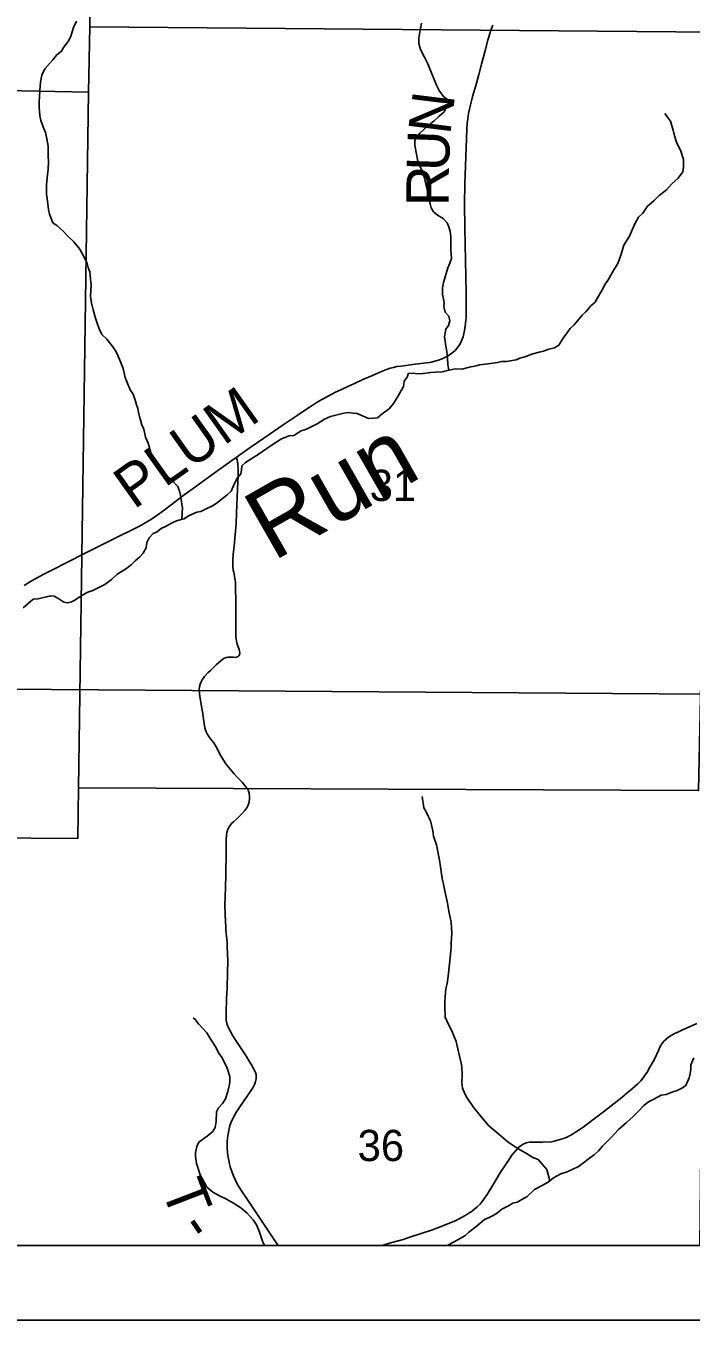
# Model space of a CAD drawing. Extents: x -19.9 to 41.9, y 0 to 32.3.
# Drawn here: x 4.075 to 4.967, y 14 to 15.736 of the extents above; entities that cross this region are included whole.
import ezdxf

# ---------------------------------------------------------------- set-up
doc = ezdxf.new("R2010")
doc.units = 0
for name, color, linetype in [('GM_X_Corporation', 7, 'Continuous'), ('GM_X_County_Road', 7, 'Continuous'), ('GM_X_County_Road_Text', 7, 'Continuous'), ('GM_X_Minor_River', 7, 'Continuous'), ('GM_X_Minor_River_Text', 7, 'Continuous'), ('GM_X_Section', 7, 'Continuous'), ('GM_X_Section_Text', 7, 'Continuous'), ('GM_X_Township_Road', 7, 'Continuous'), ('GM_X_Township_Road_Text', 7, 'Continuous'), ('SH_Data', 7, 'Continuous')]:
    doc.layers.add(name, color=color, linetype=linetype)

msp = doc.modelspace()

# ---------------------------------------------------------------- linework, layer by layer
at = {"layer": 'GM_X_Corporation'}
for points in [[(2.1, 17.918), (2.1, 14.1), (8.9, 14.1), (8.9, 17.8974), (7.9072, 17.9171), (7.5529, 17.9242), (7.3858, 17.9277), (6.9468, 17.937), (6.7, 17.9422), (6.3069, 17.9505), (6.2497, 17.9517), (6.2397, 17.9517), (5.9048, 17.9534), (5.761, 17.9543), (5.4954, 17.9559), (5.0257, 17.9637), (5.0192, 17.8403), (4.9169, 17.8392), (4.2613, 17.8672), (3.984, 17.879), (3.7505, 17.884), (2.973, 17.9007), (2.4715, 17.9106)], [(3.9969, 15.8607), (5.0009, 15.8404), (4.9872, 14.9075), (4.9863, 14.8396), (3.9837, 14.8466)], [(3.9655, 14.1), (4.9783, 14.1), (4.9863, 14.8396), (3.9837, 14.8466)]]:
    msp.add_lwpolyline(points, close=True, dxfattribs=at)
msp.add_lwpolyline([(2.1, 17.918), (2.1, 14.1), (7.8246, 14.1), (7.8518, 15.3043), (7.854, 15.4058), (7.8702, 16.1679), (7.8776, 16.5173), (7.9012, 17.4524), (7.9072, 17.9171)], dxfattribs=at)
at = {"layer": 'GM_X_County_Road'}
msp.add_lwpolyline([(4.0725, 14.9855), (4.0811, 14.9905), (4.0982, 15), (4.1107, 15.0065), (4.1526, 15.0277), (4.1884, 15.0456), (4.227, 15.065), (4.2333, 15.0684), (4.238, 15.0711), (4.2432, 15.0744), (4.2492, 15.0785), (4.2603, 15.0864), (4.2753, 15.098), (4.2872, 15.1069), (4.2993, 15.1156), (4.3193, 15.1303), (4.3508, 15.1529), (4.3569, 15.157), (4.3646, 15.1626), (4.3771, 15.1714), (4.4024, 15.1887), (4.4198, 15.2009), (4.4414, 15.2153), (4.4512, 15.2218), (4.4585, 15.2267), (4.4655, 15.2313), (4.4724, 15.2353), (4.4799, 15.2394), (4.489, 15.2441), (4.4981, 15.2482), (4.5064, 15.2521), (4.5147, 15.2558), (4.5267, 15.2614), (4.5394, 15.2671), (4.5515, 15.2723), (4.5584, 15.275), (4.5631, 15.2766), (4.5678, 15.2779), (4.5722, 15.2789), (4.5779, 15.2797), (4.5967, 15.282), (4.6161, 15.2844), (4.6183, 15.2848), (4.6233, 15.286), (4.6281, 15.2875), (4.633, 15.2894), (4.6376, 15.2915), (4.6405, 15.2932), (4.6443, 15.2957), (4.6477, 15.2984), (4.6507, 15.301), (4.6527, 15.3033), (4.6549, 15.3062), (4.6565, 15.3086), (4.6585, 15.3126), (4.6598, 15.3156), (4.661, 15.3189), (4.6621, 15.3231), (4.663, 15.3275), (4.6639, 15.3335), (4.6648, 15.3408), (4.6651, 15.3452), (4.6653, 15.3585), (4.665, 15.3781), (4.6635, 15.4641), (4.6629, 15.4971), (4.6633, 15.5242), (4.6646, 15.5604), (4.6659, 15.5972), (4.6666, 15.6049), (4.6673, 15.6114), (4.6683, 15.6182), (4.6695, 15.6241), (4.6709, 15.63), (4.6723, 15.6354), (4.6738, 15.6413), (4.6785, 15.6573), (4.6822, 15.6709), (4.6858, 15.6847), (4.6905, 15.7028), (4.6943, 15.7169), (4.6984, 15.7302), (4.701, 15.7368)], dxfattribs=at)
at = {"layer": 'GM_X_Minor_River'}
for points in [[(4.284, 15.074), (4.2844, 15.0831), (4.2847, 15.0892), (4.2834, 15.0975), (4.2822, 15.1066), (4.2809, 15.1119), (4.2786, 15.118), (4.2709, 15.1263), (4.2628, 15.133), (4.2533, 15.1397), (4.249, 15.1461), (4.2455, 15.1552), (4.2427, 15.162), (4.2387, 15.1764), (4.2352, 15.1843), (4.2328, 15.1949), (4.2304, 15.2006), (4.2288, 15.2059), (4.2272, 15.212), (4.226, 15.2177), (4.2248, 15.2226), (4.2232, 15.2275), (4.222, 15.2325), (4.2185, 15.2419), (4.2146, 15.2476), (4.2107, 15.2578), (4.2079, 15.2642), (4.2051, 15.2764), (4.2016, 15.2851), (4.1988, 15.293), (4.1953, 15.2994), (4.1899, 15.3073), (4.1833, 15.3156), (4.1768, 15.322), (4.1737, 15.3288), (4.1713, 15.3345), (4.1681, 15.3439), (4.165, 15.3549), (4.1629, 15.364), (4.1616, 15.3735), (4.1622, 15.3884), (4.1617, 15.3963), (4.1604, 15.4058), (4.1584, 15.4119), (4.1572, 15.4172), (4.1525, 15.4266), (4.1471, 15.4365), (4.139, 15.4462), (4.1313, 15.4537), (4.124, 15.4616), (4.1163, 15.4683), (4.111, 15.4717), (4.1067, 15.4834), (4.1054, 15.4895), (4.1033, 15.5043), (4.1025, 15.51), (4.1023, 15.5229), (4.104, 15.5367), (4.1046, 15.5431), (4.1052, 15.5546), (4.1048, 15.561), (4.1046, 15.5747), (4.1029, 15.5846), (4.1013, 15.593), (4.0989, 15.5982), (4.0969, 15.6039), (4.095, 15.6092), (4.0934, 15.6157), (4.0928, 15.6267), (4.0927, 15.6347), (4.093, 15.6404), (4.0936, 15.6492), (4.0946, 15.6602), (4.0964, 15.6698), (4.1004, 15.6782), (4.1108, 15.6902), (4.1164, 15.6971), (4.1228, 15.7018), (4.1254, 15.7071), (4.1324, 15.7164), (4.135, 15.7221), (4.1386, 15.7336), (4.1426, 15.742)], [(4.6419, 15.2739), (4.6413, 15.2765), (4.6404, 15.2819), (4.6399, 15.2902), (4.639, 15.2993), (4.6378, 15.3062), (4.637, 15.3126), (4.6361, 15.3187), (4.6379, 15.329), (4.6416, 15.334), (4.6434, 15.3405), (4.6418, 15.3466), (4.6368, 15.3518), (4.6351, 15.3594), (4.6354, 15.3644), (4.6346, 15.3693), (4.6334, 15.3761), (4.6333, 15.3845), (4.6347, 15.3918), (4.6404, 15.4116), (4.6434, 15.4178), (4.6456, 15.4239), (4.6451, 15.4296), (4.6446, 15.4357), (4.6444, 15.4536), (4.6435, 15.46), (4.6419, 15.4665), (4.6396, 15.4718), (4.6345, 15.4774), (4.6265, 15.4822), (4.6215, 15.4867), (4.6184, 15.492), (4.6168, 15.4973), (4.6141, 15.5064), (4.6124, 15.5193), (4.6103, 15.5276), (4.6087, 15.5333), (4.606, 15.5413), (4.6032, 15.5477), (4.6005, 15.5545), (4.598, 15.5659), (4.5964, 15.5758), (4.5963, 15.5815), (4.5985, 15.5865), (4.603, 15.5922), (4.6078, 15.5965), (4.6134, 15.6012), (4.622, 15.6085), (4.6291, 15.6147), (4.6355, 15.6205), (4.6384, 15.6259), (4.6414, 15.6309), (4.6402, 15.6373), (4.6352, 15.6407), (4.6294, 15.6482), (4.6255, 15.6565), (4.6212, 15.666), (4.6181, 15.6739), (4.6137, 15.6849), (4.6091, 15.694), (4.604, 15.7042), (4.6016, 15.7121), (4.6015, 15.7197), (4.6025, 15.7251), (4.6054, 15.7396)], [(4.6832, 15.2814), (4.6908, 15.2822), (4.6976, 15.2831), (4.707, 15.2844), (4.7127, 15.2856), (4.7191, 15.2857), (4.7323, 15.2882), (4.7372, 15.2902), (4.7436, 15.2922), (4.7546, 15.2961), (4.7629, 15.2982), (4.7689, 15.2998), (4.7761, 15.3022), (4.7836, 15.3042), (4.7892, 15.3077), (4.7944, 15.3158), (4.8044, 15.33), (4.8097, 15.335), (4.8208, 15.3478), (4.8257, 15.3524), (4.8324, 15.3605), (4.838, 15.3652), (4.8413, 15.3713), (4.8468, 15.3809), (4.8513, 15.3893), (4.8553, 15.3951), (4.8627, 15.4078), (4.8683, 15.4174), (4.8708, 15.4235), (4.873, 15.4296), (4.8766, 15.4419), (4.884, 15.4538), (4.888, 15.4633), (4.8917, 15.4714), (4.8961, 15.4795), (4.9021, 15.4849), (4.9084, 15.4941), (4.9166, 15.5011), (4.9237, 15.5084), (4.9335, 15.5158), (4.9409, 15.5239), (4.9495, 15.5316), (4.9555, 15.5401), (4.9565, 15.5462), (4.9563, 15.5569), (4.9524, 15.5694), (4.9477, 15.5784), (4.9445, 15.5883), (4.9425, 15.5962), (4.9409, 15.6019), (4.9389, 15.608), (4.9351, 15.6136), (4.9316, 15.6185)], [(4.0712, 14.9553), (4.0847, 14.967), (4.0915, 14.9675), (4.1024, 14.9703), (4.1081, 14.9715), (4.113, 14.9712), (4.1191, 14.9675), (4.1256, 14.963), (4.1306, 14.962), (4.1358, 14.9636), (4.1407, 14.9655), (4.1501, 14.9722), (4.158, 14.9765), (4.1644, 14.9785), (4.17, 14.9812), (4.1805, 14.9867), (4.1895, 14.9933), (4.1974, 15.0007), (4.2086, 15.0073), (4.2158, 15.0131), (4.2214, 15.0182), (4.2277, 15.0236), (4.2322, 15.0286), (4.2362, 15.0359), (4.2369, 15.0428), (4.2402, 15.0493), (4.2454, 15.0551), (4.2507, 15.0574), (4.2563, 15.0617), (4.262, 15.0645), (4.271, 15.0695), (4.2766, 15.0719), (4.2819, 15.0735), (4.2872, 15.0747), (4.2928, 15.0786), (4.3041, 15.0838), (4.3094, 15.0846), (4.3165, 15.0881), (4.3252, 15.0921), (4.3312, 15.0964), (4.3383, 15.1018), (4.3446, 15.1068), (4.3499, 15.1119), (4.3546, 15.1222), (4.3587, 15.1299), (4.3632, 15.1349), (4.3638, 15.1402), (4.3645, 15.146), (4.3694, 15.1502), (4.3877, 15.1619), (4.4024, 15.1724), (4.4114, 15.1779), (4.4177, 15.1822), (4.4279, 15.1861), (4.434, 15.1866), (4.4441, 15.1928), (4.4509, 15.1952), (4.4599, 15.1996), (4.4652, 15.2023), (4.4753, 15.2082), (4.4832, 15.2121), (4.4888, 15.2133), (4.4956, 15.2153), (4.5013, 15.2166), (4.5073, 15.2174), (4.5138, 15.2164), (4.5191, 15.2161), (4.526, 15.2127), (4.5343, 15.2094), (4.5415, 15.2096), (4.5464, 15.2104), (4.5524, 15.2154), (4.5618, 15.2224), (4.5677, 15.2294), (4.5733, 15.239), (4.5781, 15.2467), (4.581, 15.2524), (4.5821, 15.2593), (4.5862, 15.2647), (4.588, 15.27), (4.5963, 15.2698), (4.6012, 15.2691), (4.6073, 15.2696), (4.6179, 15.2712), (4.6239, 15.2713), (4.633, 15.2718), (4.6383, 15.2731), (4.6504, 15.2759), (4.6595, 15.2753), (4.6696, 15.2781), (4.6783, 15.2798), (4.6832, 15.2814)], [(4.645, 14.5055), (4.6459, 14.5192), (4.6449, 14.5337), (4.6425, 14.5462), (4.6396, 14.5614), (4.6371, 14.5735), (4.6347, 14.5845), (4.6331, 14.5925), (4.6306, 14.608), (4.6293, 14.6168), (4.6252, 14.6376), (4.6213, 14.649), (4.6204, 14.6562), (4.6172, 14.6695), (4.6141, 14.6759), (4.6117, 14.6816), (4.6082, 14.6869), (4.6061, 14.7021)], [(4.7772, 14.187), (4.7732, 14.2022), (4.7616, 14.2153), (4.7544, 14.2179), (4.7445, 14.2242), (4.7349, 14.2298), (4.7215, 14.2387), (4.7089, 14.2492), (4.6955, 14.2608), (4.6858, 14.272), (4.6747, 14.286), (4.6661, 14.2988), (4.6634, 14.3037), (4.6603, 14.3112), (4.6594, 14.3181), (4.6596, 14.3291), (4.6595, 14.3398), (4.6583, 14.3447), (4.655, 14.3599), (4.6518, 14.3735), (4.6487, 14.3811), (4.6459, 14.3879), (4.6416, 14.3966), (4.6369, 14.4064), (4.6363, 14.4209), (4.6363, 14.4258), (4.6369, 14.4342), (4.6379, 14.4445), (4.6397, 14.4517), (4.6414, 14.4647), (4.6417, 14.4697), (4.6434, 14.4819), (4.645, 14.5002), (4.645, 14.5055)], [(4.3949, 14.1), (4.3922, 14.1058), (4.3878, 14.1191), (4.3839, 14.1278), (4.3797, 14.1345), (4.3716, 14.1436), (4.3631, 14.1507), (4.3532, 14.157), (4.3437, 14.1622), (4.3345, 14.1666), (4.3257, 14.1718), (4.3173, 14.1785), (4.3138, 14.1849), (4.3087, 14.1947), (4.3052, 14.2046), (4.3036, 14.2099), (4.3023, 14.2194), (4.3022, 14.2247), (4.304, 14.2327), (4.3066, 14.2388), (4.3178, 14.2466), (4.3253, 14.2528), (4.3286, 14.2582), (4.33, 14.2666), (4.3306, 14.2792), (4.3332, 14.2849), (4.3384, 14.2907), (4.3425, 14.2969), (4.3457, 14.3068), (4.3479, 14.316), (4.3482, 14.3209), (4.3481, 14.3266), (4.3449, 14.338), (4.3379, 14.3516), (4.3336, 14.358), (4.3286, 14.3675), (4.3227, 14.3765), (4.3173, 14.3855), (4.3123, 14.3912), (4.3065, 14.3976), (4.3023, 14.4028), (4.2991, 14.4053)], [(4.8802, 14.2651), (4.8888, 14.2732), (4.8951, 14.2794), (4.9033, 14.2879), (4.9097, 14.2929), (4.9168, 14.2965), (4.9266, 14.3016), (4.9334, 14.3024), (4.942, 14.306), (4.9481, 14.308), (4.9541, 14.3111), (4.9597, 14.3146), (4.9641, 14.325), (4.9652, 14.3307), (4.9662, 14.3368), (4.9665, 14.3425), (4.9705, 14.3517)], [(4.6395, 14.1), (4.6489, 14.1048), (4.6632, 14.113), (4.6688, 14.118), (4.6782, 14.125), (4.6897, 14.1351), (4.6958, 14.1378), (4.7014, 14.1402), (4.707, 14.1437), (4.713, 14.1488), (4.722, 14.1535), (4.7277, 14.157), (4.7337, 14.1582), (4.7468, 14.166), (4.7565, 14.1753), (4.7663, 14.18), (4.775, 14.1851), (4.7821, 14.1909), (4.7918, 14.196), (4.8005, 14.1988), (4.8061, 14.2016), (4.8159, 14.2059), (4.8242, 14.2121), (4.8305, 14.2171), (4.8369, 14.2218), (4.8425, 14.2272), (4.8481, 14.2334), (4.8544, 14.24), (4.86, 14.2454), (4.8693, 14.2558), (4.8802, 14.2651)]]:
    msp.add_lwpolyline(points, dxfattribs=at)
at = {"layer": 'GM_X_Section'}
for points in [[(4.1751, 16.7729), (5.0099, 16.7619), (4.9984, 15.7274), (4.1607, 15.7345), (4.1739, 16.6474)], [(4.1739, 16.6474), (4.1607, 15.7345), (4.1589, 15.6469), (3.155, 15.6672), (3.1702, 16.6786)], [(4.9984, 15.7274), (4.9768, 14.7102), (4.1452, 14.714), (4.1589, 15.6469), (4.1607, 15.7345)], [(3.155, 15.6672), (4.1589, 15.6469), (4.1452, 14.714), (4.1443, 14.6461), (3.1417, 14.6532)]]:
    msp.add_lwpolyline(points, close=True, dxfattribs=at)
at = {"layer": 'GM_X_Township_Road'}
for points in [[(4.3563, 14.9371), (4.3564, 14.9637), (4.3561, 14.983), (4.3557, 14.9894), (4.3551, 14.9951), (4.3536, 15.003), (4.3529, 15.006), (4.3523, 15.0107), (4.3522, 15.0125), (4.3524, 15.0194), (4.3529, 15.0271), (4.3538, 15.0344), (4.3547, 15.0427), (4.3552, 15.049), (4.356, 15.0582), (4.3567, 15.0684), (4.3574, 15.0824), (4.3586, 15.1148), (4.3593, 15.1324), (4.3595, 15.1392), (4.3589, 15.1488), (4.3586, 15.1505), (4.3579, 15.1539), (4.3569, 15.157)], [(4.3461, 14.393), (4.3452, 14.395), (4.3443, 14.3979), (4.3437, 14.4), (4.3434, 14.4023), (4.3433, 14.4047), (4.3434, 14.419), (4.3436, 14.4249), (4.3439, 14.4308), (4.3443, 14.4385), (4.3446, 14.4451), (4.3449, 14.4523), (4.3451, 14.4593), (4.3453, 14.4653), (4.3455, 14.4818), (4.3448, 14.5011), (4.3445, 14.5063), (4.3441, 14.5115), (4.3435, 14.5185), (4.3431, 14.5234), (4.3428, 14.528), (4.3426, 14.534), (4.3421, 14.5447), (4.3418, 14.5564), (4.3424, 14.58), (4.3427, 14.5977), (4.3433, 14.6276), (4.3434, 14.6437), (4.344, 14.6513), (4.3444, 14.6542), (4.345, 14.6567), (4.3459, 14.6595), (4.3472, 14.6616), (4.3507, 14.666), (4.3532, 14.6685), (4.3571, 14.672), (4.3643, 14.6792), (4.3682, 14.6835), (4.3709, 14.6873), (4.3725, 14.6897), (4.3738, 14.6933), (4.3745, 14.6983), (4.3747, 14.7019), (4.3744, 14.7072), (4.3735, 14.7096), (4.3728, 14.7111), (4.3702, 14.7146), (4.368, 14.7176), (4.3647, 14.7215), (4.3618, 14.7248), (4.3577, 14.7287), (4.3542, 14.7328), (4.3491, 14.7387), (4.3431, 14.7463), (4.3398, 14.7511), (4.3364, 14.7568), (4.3341, 14.7609), (4.3322, 14.7649), (4.33, 14.7688), (4.3268, 14.7741), (4.3238, 14.778), (4.32, 14.7827), (4.3177, 14.7865), (4.3165, 14.7891), (4.3158, 14.7913), (4.3149, 14.7944), (4.3132, 14.8062), (4.312, 14.8135), (4.3103, 14.8231), (4.3091, 14.8316), (4.3082, 14.8364), (4.3076, 14.8405), (4.3072, 14.8454), (4.3075, 14.8497), (4.3084, 14.853), (4.3097, 14.8561), (4.3113, 14.859), (4.3136, 14.8621), (4.3145, 14.8633), (4.3189, 14.8681), (4.3222, 14.8713), (4.3253, 14.8743), (4.33, 14.8789), (4.3336, 14.8822), (4.3363, 14.8844), (4.339, 14.8865), (4.3409, 14.8877), (4.3424, 14.8885), (4.3434, 14.8889), (4.3462, 14.8892), (4.3532, 14.889), (4.3553, 14.8889), (4.3572, 14.8892), (4.3584, 14.8896), (4.3599, 14.8906), (4.3607, 14.8915), (4.3612, 14.8926), (4.3616, 14.8938), (4.3613, 14.8977), (4.3608, 14.8994), (4.3589, 14.9045), (4.3581, 14.9068), (4.357, 14.9113), (4.3567, 14.913), (4.3562, 14.9178), (4.3562, 14.9221), (4.3563, 14.9361), (4.3563, 14.9371)], [(4.4131, 14.1), (4.4131, 14.1001), (4.4062, 14.1101), (4.3904, 14.1339), (4.3716, 14.162), (4.3648, 14.1722), (4.3601, 14.1797), (4.3573, 14.1846), (4.3549, 14.1894), (4.3532, 14.1933), (4.3513, 14.1982), (4.3489, 14.2057), (4.3473, 14.2117), (4.3464, 14.2161), (4.3456, 14.2209), (4.3452, 14.2253), (4.3448, 14.2311), (4.3447, 14.2373), (4.3448, 14.2399), (4.3455, 14.2471), (4.3459, 14.2496), (4.3468, 14.2541), (4.3479, 14.2589), (4.3485, 14.2611), (4.3502, 14.2657), (4.3516, 14.2687), (4.3551, 14.2755), (4.3573, 14.2793), (4.3609, 14.2849), (4.3772, 14.3089), (4.379, 14.3117), (4.3809, 14.3151), (4.3818, 14.3171), (4.3828, 14.3201), (4.3836, 14.3236), (4.3837, 14.3261), (4.3834, 14.3295), (4.3828, 14.3319), (4.3818, 14.3341), (4.3799, 14.3376), (4.3773, 14.3422), (4.3741, 14.3474), (4.371, 14.3529), (4.3689, 14.3561), (4.3572, 14.3737), (4.3524, 14.3813), (4.3491, 14.3871), (4.3471, 14.3911), (4.3461, 14.393)], [(4.9516, 14.3876), (4.9533, 14.3884), (4.9744, 14.398)], [(4.6701, 14.1443), (4.6718, 14.1454), (4.6762, 14.1487), (4.68, 14.1519), (4.6837, 14.1554), (4.6866, 14.1589), (4.689, 14.1623), (4.6932, 14.1686), (4.7023, 14.1831), (4.7113, 14.1985), (4.7178, 14.2083), (4.723, 14.2163), (4.7262, 14.2211), (4.7294, 14.225), (4.7324, 14.2284), (4.7347, 14.2311), (4.7375, 14.2334), (4.7414, 14.2358), (4.7457, 14.2376), (4.7501, 14.2385), (4.7542, 14.2388), (4.7619, 14.2387), (4.7677, 14.2385), (4.7794, 14.2393), (4.7832, 14.24), (4.7879, 14.2412), (4.7926, 14.2426), (4.7981, 14.2447), (4.8008, 14.2459), (4.8065, 14.2486), (4.8118, 14.2519), (4.8165, 14.255), (4.822, 14.2589), (4.8438, 14.2752), (4.8493, 14.2795), (4.8736, 14.2986), (4.881, 14.3047), (4.8848, 14.3079), (4.8953, 14.3168), (4.897, 14.3185), (4.8993, 14.3209), (4.9009, 14.323), (4.9085, 14.3341), (4.9102, 14.3369), (4.9157, 14.3467), (4.9179, 14.351), (4.9228, 14.3618), (4.9254, 14.3668), (4.9274, 14.3704), (4.9302, 14.3741), (4.9332, 14.377), (4.9368, 14.3801), (4.9408, 14.3823), (4.9445, 14.3844), (4.9481, 14.3859), (4.9516, 14.3876)], [(4.5523, 14.1), (4.5563, 14.1014), (4.5622, 14.1031), (4.5805, 14.1083), (4.5882, 14.1107), (4.6198, 14.121), (4.6282, 14.124), (4.634, 14.1263), (4.6502, 14.1333), (4.6539, 14.135), (4.6648, 14.1409), (4.6675, 14.1426), (4.6701, 14.1443)]]:
    msp.add_lwpolyline(points, dxfattribs=at)
at = {"layer": 'SH_Data'}
for p, q in [((2.1, 14.1), (8.9, 14.1)), ((2, 14), (9, 14))]:
    msp.add_line(p, q, dxfattribs=at)

# ---------------------------------------------------------------- texts
at = {"layer": 'GM_X_County_Road_Text'}
for s, height, rotation, p in [('N', 0.0568, 82.9111, (4.6436, 15.5887)), ('U', 0.0568, 87.9815, (4.6419, 15.5401)), ('R', 0.0568, 89.9063, (4.6418, 15.4939)), ('PLUM', 0.05682, 35.375, (4.2196, 15.0865))]:
    msp.add_text(s, height=height, rotation=rotation, dxfattribs=at).set_placement(p)
at = {"layer": 'GM_X_Minor_River_Text'}
msp.add_text('Run', height=0.09469, rotation=29.6968, dxfattribs=at).set_placement((4.4062, 15.017))
at = {"layer": 'GM_X_Section_Text'}
for s, p in [('31', (4.5358, 15.0987)), ('36', (4.5196, 14.2133))]:
    msp.add_text(s, height=0.04186, rotation=0, dxfattribs=at).set_placement(p)
at = {"layer": 'GM_X_Township_Road_Text'}
for s, rotation, p in [('T', 291.0461, (4.256, 14.176)), ('-', 304.6693, (4.2781, 14.1233))]:
    msp.add_text(s, height=0.0568, rotation=rotation, dxfattribs=at).set_placement(p)

doc.saveas('drawing.dxf')
